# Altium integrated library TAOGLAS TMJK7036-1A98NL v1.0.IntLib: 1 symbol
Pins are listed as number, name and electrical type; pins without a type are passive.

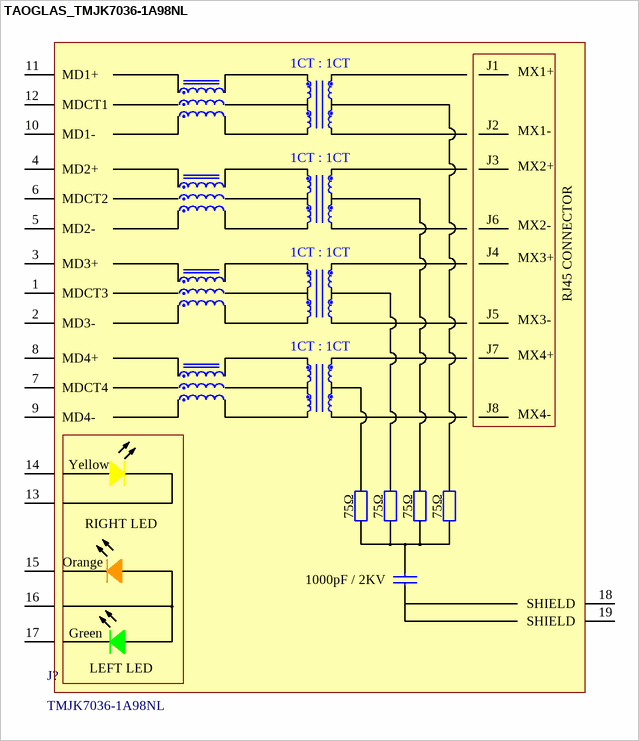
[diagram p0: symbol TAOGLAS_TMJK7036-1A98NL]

## TAOGLAS_TMJK7036-1A98NL
designator J?, comment TMJK7036-1A98NL
RJ45 connector with integrated magnetics 1G Base-T Single Port Tab-UP with right angle THT mount and LEDs; ComponentLibStatus: Created; MFG: Taoglas; Temp_High: +85C; Temp_Low: -40C
footprint TAOGLAS_TMJK7036-1A98NL (RJ45 connector with integrated magnetics 1G Base-T Single Port Tab-UP with right angle THT mount and LEDs)
pins: 1 MDCT3, 2 MD3-, 3 MD3+, 4 MD2+, 5 MD2-, 6 MDCT2, 7 MDCT4, 8 MD4+, 9 MD4-, 10 MD1-, 11 MD1+, 12 MDCT1, 13, 14, 15, 16, 17, 18 SHIELD, 19 SHIELD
